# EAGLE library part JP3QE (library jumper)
JUMPER
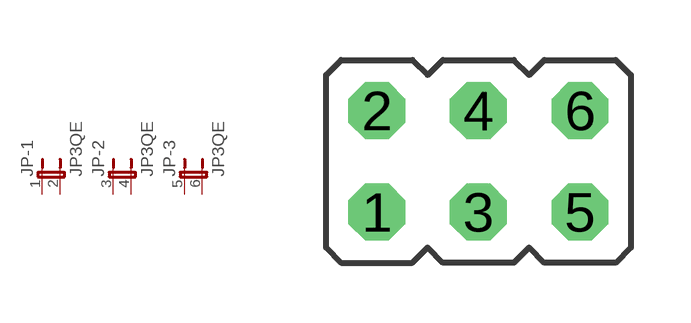
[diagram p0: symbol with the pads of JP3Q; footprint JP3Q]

Designator prefix JP; gates -1=JP2E -2=JP2E -3=JP2E

## JP3QE  [JP3Q]
1  -1:1  pas
2  -1:2  pas
3  -2:1  pas
4  -2:2  pas
5  -3:1  pas
6  -3:2  pas

## Footprint JP3Q (pad centres in mm)
JUMPER
drill 0.914 octagon: 1 -2.54,-1.27; 2 -2.54,1.27; 3 0,-1.27; 4 0,1.27; 5 2.54,-1.27; 6 2.54,1.27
